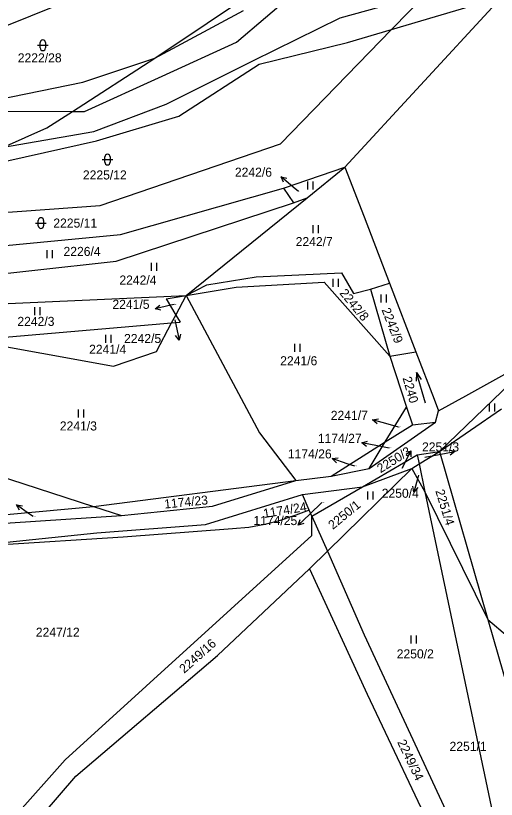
# Model space of a CAD drawing. Extents: x -785744 to -782822, y -1067550 to -1063910.
# Drawn here: x -785048 to -784957.9, y -1066077.4 to -1065930.4 of the extents above; entities that cross this region are included whole.
import ezdxf

# ---------------------------------------------------------------- set-up
doc = ezdxf.new("R2010")
doc.units = 0
for name, color, linetype in [('Hranice parcel', 7, 'Continuous'), ('Parcelní čísla', 7, 'Continuous'), ('Pop_ČP_popisy', 7, 'Continuous'), ('Vnitřní kresba', 7, 'Continuous'), ('Značky kultur', 7, 'Continuous')]:
    doc.layers.add(name, color=color, linetype=linetype)

msp = doc.modelspace()

# ---------------------------------------------------------------- linework, layer by layer
at = {"layer": 'Hranice parcel'}
for p, q in [((-784992.93, -1066023.12), (-784994.2, -1066020.23)), ((-784995.45, -1066024.06), (-784997.22, -1066024.65)), ((-784992.93, -1066023.12), (-784995.45, -1066024.06)), ((-784992.42, -1066024.28), (-784992.93, -1066023.12)), ((-785004.27, -1066026.3), (-785001.28, -1066025.76)), ((-785001.28, -1066025.76), (-784998.33, -1066025.02)), ((-784998.33, -1066025.02), (-784997.22, -1066024.65)), ((-785027.83, -1066028.15), (-785007.29, -1066026.61)), ((-785007.29, -1066026.61), (-785004.27, -1066026.3)), ((-785051.88, -1066029.7), (-785027.83, -1066028.15))]:
    msp.add_line(p, q, dxfattribs=at)
for points in [[(-785021.86, -1065938.32), (-785002.25, -1065925.15)], [(-785061.19, -1065936.82), (-785034.57, -1065926.04)], [(-784977.5, -1065932.93), (-784970.84, -1065926.08)], [(-784986.24, -1065958.8), (-784957.92, -1065928.01)], [(-784977.5, -1065932.93), (-784959.95, -1065927.74)], [(-785021.86, -1065938.32), (-785005.23, -1065929.39)], [(-784998.34, -1065954.39), (-784977.5, -1065932.93)], [(-784985.74, -1065935.37), (-784977.5, -1065932.93)], [(-785002.34, -1065939.45), (-784985.74, -1065935.37)], [(-785037.32, -1065948.32), (-785021.86, -1065938.32)], [(-785035.38, -1065942.82), (-785021.86, -1065938.32)], [(-785017.38, -1065949.2), (-785002.34, -1065939.45)], [(-785064.76, -1065948.83), (-785035.38, -1065942.82)], [(-785042.09, -1065951.4), (-785037.32, -1065948.32)], [(-785032.78, -1065953.85), (-785017.38, -1065949.2)], [(-785050.26, -1065955.05), (-785042.09, -1065951.4)], [(-785062.65, -1065960.56), (-785032.78, -1065953.85)], [(-785032.15, -1065965.98), (-784998.34, -1065954.39)], [(-784997.73, -1065962.7), (-784986.24, -1065958.8)], [(-784993.35, -1065964.54), (-784986.24, -1065958.8)], [(-784986.24, -1065958.8), (-784982.66, -1065968.13)], [(-785028.32, -1065971.4), (-784997.73, -1065962.7)], [(-784997.73, -1065962.7), (-784995.9, -1065965.45)], [(-785029.1, -1065976.39), (-784995.9, -1065965.45)], [(-785016.02, -1065982.85), (-784993.35, -1065964.54)], [(-784995.9, -1065965.45), (-784993.35, -1065964.54)], [(-785083.14, -1065969.66), (-785032.15, -1065965.98)], [(-784982.66, -1065968.13), (-784977.89, -1065980.54)], [(-785062.95, -1065974.73), (-785028.32, -1065971.4)], [(-785060.8, -1065979.91), (-785029.1, -1065976.39)], [(-785002.9, -1065979.36), (-784986.86, -1065978.61)], [(-784986.86, -1065978.61), (-784984.65, -1065982.49)], [(-785012.14, -1065980.87), (-785002.9, -1065979.36)], [(-785006.62, -1065981.27), (-784990.13, -1065980.37)], [(-784990.13, -1065980.37), (-784977.83, -1065994.22)], [(-785016.02, -1065982.85), (-785012.14, -1065980.87)], [(-785016.02, -1065982.85), (-785006.62, -1065981.27)], [(-784984.65, -1065982.49), (-784981.46, -1065981.65)], [(-784981.46, -1065981.65), (-784977.89, -1065980.54)], [(-784981.46, -1065981.65), (-784977.83, -1065994.22)], [(-784977.89, -1065980.54), (-784972.95, -1065993.42)], [(-785073.11, -1065985.43), (-785016.02, -1065982.85)], [(-785019.74, -1065983.48), (-785016.02, -1065982.85)], [(-785017.95, -1065986.52), (-785016.02, -1065982.85)], [(-785016.02, -1065982.85), (-785002.27, -1066008.63)], [(-785019.74, -1065983.48), (-785017.95, -1065986.52)], [(-785018.73, -1065988.01), (-785017.95, -1065986.52)], [(-785017.95, -1065986.52), (-785017.15, -1065987.87)], [(-784963.61, -1066001.67), (-784938.18, -1065987.54)], [(-785056.54, -1065991.24), (-785018.73, -1065988.01)], [(-785021.54, -1065993.34), (-785018.73, -1065988.01)], [(-785018.73, -1065988.01), (-785017.15, -1065987.87)], [(-785056.54, -1065991.24), (-785029.64, -1065996.14)], [(-785029.64, -1065996.14), (-785021.54, -1065993.34)], [(-784977.83, -1065994.22), (-784972.95, -1065993.42)], [(-784972.95, -1065993.42), (-784969.53, -1066002.33)], [(-784977.83, -1065994.22), (-784974.69, -1066003.81)], [(-784968.55, -1066012.13), (-784955.15, -1065999.22)], [(-784969.53, -1066002.33), (-784968.7, -1066004.5)], [(-784968.7, -1066004.5), (-784963.61, -1066001.67)], [(-784978.69, -1066010.33), (-784974.69, -1066003.81)], [(-784974.69, -1066003.81), (-784973.61, -1066007.11)], [(-784969.26, -1066006.62), (-784968.7, -1066004.5)], [(-784968.55, -1066012.13), (-784956.88, -1066004.14)], [(-784981.73, -1066015.31), (-784969.26, -1066006.62)], [(-784973.61, -1066007.11), (-784969.26, -1066006.62)], [(-784978.69, -1066010.33), (-784973.61, -1066007.11)], [(-785002.27, -1066008.63), (-784995.43, -1066017.59)], [(-784988.81, -1066016.74), (-784978.69, -1066010.33)], [(-784981.73, -1066015.31), (-784978.69, -1066010.33)], [(-784982.98, -1066018.76), (-784972.71, -1066012.75)], [(-784972.71, -1066012.75), (-784968.55, -1066012.13)], [(-784972.71, -1066012.75), (-784972.35, -1066014.46)], [(-784972.35, -1066014.46), (-784968.55, -1066012.13)], [(-784968.55, -1066012.13), (-784959.46, -1066043.64)], [(-785054.34, -1066015.63), (-785033.4, -1066022.44)], [(-784989.52, -1066030.86), (-784973.71, -1066015.3)], [(-784988.81, -1066016.74), (-784981.73, -1066015.31)], [(-784982.98, -1066018.76), (-784973.71, -1066015.3)], [(-784973.71, -1066015.3), (-784972.35, -1066014.46)], [(-784973.71, -1066015.3), (-784971.25, -1066019.67)], [(-784972.35, -1066014.46), (-784971.25, -1066019.67)], [(-784995.43, -1066017.59), (-784988.81, -1066016.74)], [(-785033.4, -1066022.44), (-784995.43, -1066017.59)], [(-785011.07, -1066022.36), (-784995.43, -1066017.59)], [(-784994.2, -1066020.23), (-784982.98, -1066018.76)], [(-784992.42, -1066024.28), (-784982.98, -1066018.76)], [(-784971.25, -1066019.67), (-784954.2, -1066100.68)], [(-784971.25, -1066019.67), (-784959.46, -1066043.64)], [(-785012.35, -1066025.82), (-784994.2, -1066020.23)], [(-785075.56, -1066026.34), (-785033.4, -1066022.44)], [(-785033.4, -1066022.44), (-785028.11, -1066024.16)], [(-785028.11, -1066024.16), (-785011.07, -1066022.36)], [(-785075.61, -1066027.25), (-785028.11, -1066024.16)], [(-784992.43, -1066027.9), (-784992.42, -1066024.28)], [(-784992.42, -1066024.28), (-784989.52, -1066030.86)], [(-785032.76, -1066027.39), (-785012.35, -1066025.82)], [(-785051.46, -1066029.3), (-785032.76, -1066027.39)], [(-785038.66, -1066070.01), (-784992.43, -1066027.9)], [(-784992.86, -1066034.14), (-784989.52, -1066030.86)], [(-784989.52, -1066030.86), (-784982.62, -1066046.54)], [(-785010.15, -1066050.38), (-784992.86, -1066034.14)], [(-784992.86, -1066034.14), (-784982.09, -1066057.69)], [(-784959.46, -1066043.64), (-784949.82, -1066077.06)], [(-784959.46, -1066043.64), (-784952.12, -1066049.9)], [(-784982.62, -1066046.54), (-784949.13, -1066118.66)], [(-785036.7, -1066073.08), (-785010.15, -1066050.38)], [(-784982.09, -1066057.69), (-784968.63, -1066086.07)], [(-785048.24, -1066080.73), (-785038.66, -1066070.01)], [(-785042.82, -1066080.18), (-785036.7, -1066073.08)]]:
    msp.add_lwpolyline(points, dxfattribs=at)
at = {"layer": 'Pop_ČP_popisy'}
for p, q in [((-784995.93, -1065962.52), (-784998.21, -1065960.57)), ((-785018.9, -1065984.7), (-785021.82, -1065985.37)), ((-785017.93, -1065988.28), (-785017.34, -1065991.22)), ((-784978.16, -1066007.02), (-784981.05, -1066006.2)), ((-784980.13, -1066011.07), (-784983.08, -1066010.51)), ((-784975.22, -1066014.67), (-784973.87, -1066011.99)), ((-784968.59, -1066012.68), (-784965.64, -1066012.12)), ((-784985.8, -1066014.42), (-784988.63, -1066013.43)), ((-784972.52, -1066016.85), (-784973.33, -1066019.74)), ((-785045.34, -1066023.87), (-785047.78, -1066022.12)), ((-784992.83, -1066023.87), (-784995, -1066025.94))]:
    msp.add_line(p, q, dxfattribs=at)
for points in [[(-784997.77, -1065961.6), (-784998.21, -1065960.57), (-784997.12, -1065960.84)], [(-784994.96, -1065963.36), (-784995.93, -1065962.52)], [(-785020.74, -1065985.63), (-785021.82, -1065985.37), (-785020.96, -1065984.66)], [(-785018.27, -1065984.56), (-785018.9, -1065984.7)], [(-785018.1, -1065987.44), (-785017.93, -1065988.28)], [(-785017.05, -1065990.14), (-785017.34, -1065991.22), (-785018.03, -1065990.34)], [(-784980.22, -1066006.95), (-784981.05, -1066006.2), (-784979.95, -1066005.99)], [(-784976.23, -1066007.57), (-784978.16, -1066007.02)], [(-784982.19, -1066011.19), (-784983.08, -1066010.51), (-784982, -1066010.21)], [(-784977.95, -1066011.48), (-784980.13, -1066011.07)], [(-784974.76, -1066012.66), (-784973.87, -1066011.99), (-784973.87, -1066013.11)], [(-784971.27, -1066013.18), (-784968.59, -1066012.68)], [(-784966.72, -1066011.82), (-784965.64, -1066012.12), (-784966.53, -1066012.8)], [(-784987.85, -1066014.23), (-784988.63, -1066013.43), (-784987.52, -1066013.29)], [(-784984.42, -1066014.9), (-784985.8, -1066014.42)], [(-784975.51, -1066015.23), (-784975.22, -1066014.67)], [(-784972.43, -1066016.55), (-784972.52, -1066016.85)], [(-784972.58, -1066018.91), (-784973.33, -1066019.74), (-784973.54, -1066018.64)], [(-785047.26, -1066023.11), (-785047.78, -1066022.12), (-785046.67, -1066022.3)], [(-784990.58, -1066021.73), (-784992.83, -1066023.87)], [(-785044.68, -1066024.35), (-785045.34, -1066023.87)], [(-784993.93, -1066025.61), (-784995, -1066025.94), (-784994.62, -1066024.89)]]:
    msp.add_lwpolyline(points, dxfattribs=at)
at = {"layer": 'Vnitřní kresba'}
for points in [[(-785006.57, -1065935.3), (-784990.26, -1065921.36)], [(-784987.14, -1065930.75), (-784974.65, -1065927.26)], [(-785003.39, -1065938.74), (-784987.14, -1065930.75)], [(-785020.5, -1065941.68), (-785006.57, -1065935.3)], [(-785019.74, -1065946.94), (-785003.39, -1065938.74)], [(-785035.05, -1065948.32), (-785020.5, -1065941.68)], [(-785033.28, -1065952.11), (-785019.74, -1065946.94)], [(-785050.64, -1065948.3), (-785037.32, -1065948.32)], [(-785037.32, -1065948.32), (-785035.05, -1065948.32)], [(-785050.26, -1065955.05), (-785033.28, -1065952.11)]]:
    msp.add_lwpolyline(points, dxfattribs=at)
at = {"layer": 'Značky kultur'}
for p, q in [((-785043.87, -1065935.92), (-785041.87, -1065935.92)), ((-785043.37, -1065936.42), (-785043.37, -1065935.42)), ((-785042.37, -1065935.42), (-785042.37, -1065936.42)), ((-785031.24, -1065957.86), (-785031.24, -1065956.86)), ((-785030.24, -1065956.86), (-785030.24, -1065957.86)), ((-785031.74, -1065957.36), (-785029.74, -1065957.36)), ((-784993.22, -1065962.96), (-784993.22, -1065961.46)), ((-784992.22, -1065962.96), (-784992.22, -1065961.46)), ((-785044.22, -1065969.26), (-785042.22, -1065969.26)), ((-785043.72, -1065969.76), (-785043.72, -1065968.76)), ((-785042.72, -1065968.76), (-785042.72, -1065969.76)), ((-784992.18, -1065971.19), (-784992.18, -1065969.69)), ((-784991.18, -1065971.19), (-784991.18, -1065969.69)), ((-785042.06, -1065975.88), (-785042.06, -1065974.38)), ((-785041.06, -1065975.88), (-785041.06, -1065974.38)), ((-785022.48, -1065978.26), (-785022.48, -1065976.76)), ((-785021.48, -1065978.26), (-785021.48, -1065976.76)), ((-784988.47, -1065981.25), (-784988.47, -1065979.75)), ((-784987.47, -1065981.25), (-784987.47, -1065979.75)), ((-784979.45, -1065984.17), (-784979.45, -1065982.67)), ((-784978.45, -1065984.17), (-784978.45, -1065982.67)), ((-785044.34, -1065986.52), (-785044.34, -1065985.02)), ((-785043.34, -1065986.52), (-785043.34, -1065985.02)), ((-785031.03, -1065991.75), (-785031.03, -1065990.25)), ((-785030.03, -1065991.75), (-785030.03, -1065990.25)), ((-784995.62, -1065993.46), (-784995.62, -1065991.96)), ((-784994.62, -1065993.46), (-784994.62, -1065991.96)), ((-784959.16, -1066004.65), (-784959.16, -1066003.15)), ((-784958.16, -1066004.65), (-784958.16, -1066003.15)), ((-785036.17, -1066005.77), (-785036.17, -1066004.27)), ((-785035.17, -1066005.77), (-785035.17, -1066004.27)), ((-784981.95, -1066021.12), (-784981.95, -1066019.62)), ((-784980.95, -1066021.12), (-784980.95, -1066019.62)), ((-784973.85, -1066048.14), (-784973.85, -1066046.64)), ((-784972.85, -1066048.14), (-784972.85, -1066046.64))]:
    msp.add_line(p, q, dxfattribs=at)
for points in [[(-784971.12, -1066003.09), (-784972.84, -1065997.33), (-784972.89, -1065998.91)], [(-784972.84, -1065997.33), (-784971.93, -1065998.63)]]:
    msp.add_lwpolyline(points, dxfattribs=at)
for centre, start, end in [((-785042.87, -1065935.42), 0, 180), ((-785042.87, -1065936.42), 180, 0), ((-785030.74, -1065956.86), 0, 180), ((-785030.74, -1065957.86), 180, 0), ((-785043.22, -1065968.76), 0, 180), ((-785043.22, -1065969.76), 180, 0)]:
    msp.add_arc(centre, 0.5, start, end, dxfattribs=at)

# ---------------------------------------------------------------- texts
at = {"layer": 'Parcelní čísla'}
for s, height, p in [('2222/28', 1.7, (-785047.56, -1065939.12)), ('2225/12', 1.7, (-785035.36, -1065961.09)), ('2242/6', 0.1, (-784994.96, -1065963.36)), ('2225/11', 1.7, (-785040.9, -1065970.12)), ('2242/7', 1.7, (-784995.48, -1065973.6)), ('2226/4', 1.7, (-785038.99, -1065975.44)), ('2242/4', 1.7, (-785028.52, -1065980.81)), ('2241/5', 0.1, (-785018.27, -1065984.56)), ('2242/3', 1.7, (-785047.64, -1065988.57)), ('2242/5', 0.1, (-785018.1, -1065987.44)), ('2241/4', 1.7, (-785034.19, -1065993.8)), ('2241/6', 1.7, (-784998.38, -1065995.96)), ('2241/3', 1.7, (-785039.68, -1066008.19)), ('2241/7', 0.1, (-784976.23, -1066007.57)), ('1174/27', 0.1, (-784977.95, -1066011.48)), ('2251/3', 0.1, (-784971.27, -1066013.18)), ('1174/26', 0.1, (-784984.42, -1066014.9)), ('2250/3', 0.1, (-784975.51, -1066015.23)), ('2250/4', 0.1, (-784972.82, -1066016.28)), ('1174/25', 0.1, (-784990.58, -1066021.73)), ('1174/22', 0.1, (-785044.68, -1066024.35)), ('2247/12', 1.7, (-785044.18, -1066046.89)), ('2250/2', 1.7, (-784976.54, -1066050.95))]:
    msp.add_text(s, height=height, dxfattribs=at).set_placement(p)
for s, rotation, p in [('2242/8', 309.5654, (-784987.35, -1065982.46)), ('2242/9', 291.5159, (-784979.41, -1065985.55)), ('2240', 286.0352, (-784975.46, -1065998.35)), ('2251/4', 286.9612, (-784969.32, -1066019.52)), ('1174/23', 5.6774, (-785020.03, -1066022.85)), ('2250/1', 39.4996, (-784988.51, -1066026.86)), ('1174/24', 9.3619, (-785001.42, -1066024.62)), ('2249/34', 295.6557, (-784976.48, -1066066.67))]:
    msp.add_text(s, height=1.7, rotation=rotation, dxfattribs=at).set_placement(p)
at = {"layer": 'Pop_ČP_popisy'}
for s, p in [('2242/6', (-785006.87, -1065960.57)), ('2241/5', (-785029.82, -1065985.37)), ('2242/5', (-785027.64, -1065991.78)), ('2241/7', (-784988.9, -1066006.2)), ('1174/27', (-784991.33, -1066010.51)), ('2251/3', (-784971.8, -1066012.12)), ('1174/26', (-784996.95, -1066013.43)), ('2250/4', (-784979.35, -1066020.81)), ('1174/25', (-785003.4, -1066025.94)), ('2251/1', (-784966.64, -1066068.3))]:
    msp.add_text(s, height=1.7, dxfattribs=at).set_placement(p)
for s, rotation, p in [('2250/3', 32.0468, (-784979.57, -1066016.23)), ('2249/16', 41.5784, (-785016.37, -1066053.85))]:
    msp.add_text(s, height=1.7, rotation=rotation, dxfattribs=at).set_placement(p)

doc.saveas('drawing.dxf')
